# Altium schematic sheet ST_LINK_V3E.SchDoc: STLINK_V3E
size A3; Date: Not used; ApprovedBy: Not used; CheckedBy: Not used; Author: Not used; CompanyName: STMicroelectronics; DrawnBy: Not used; Engineer: Not used; Organization: Not used; Address1: Not used; Address2: Not used; Address3: Not used; Address4: Not used; DocumentNumber: 10; Revision: Not used; SheetNumber: 9; SheetTotal: 9
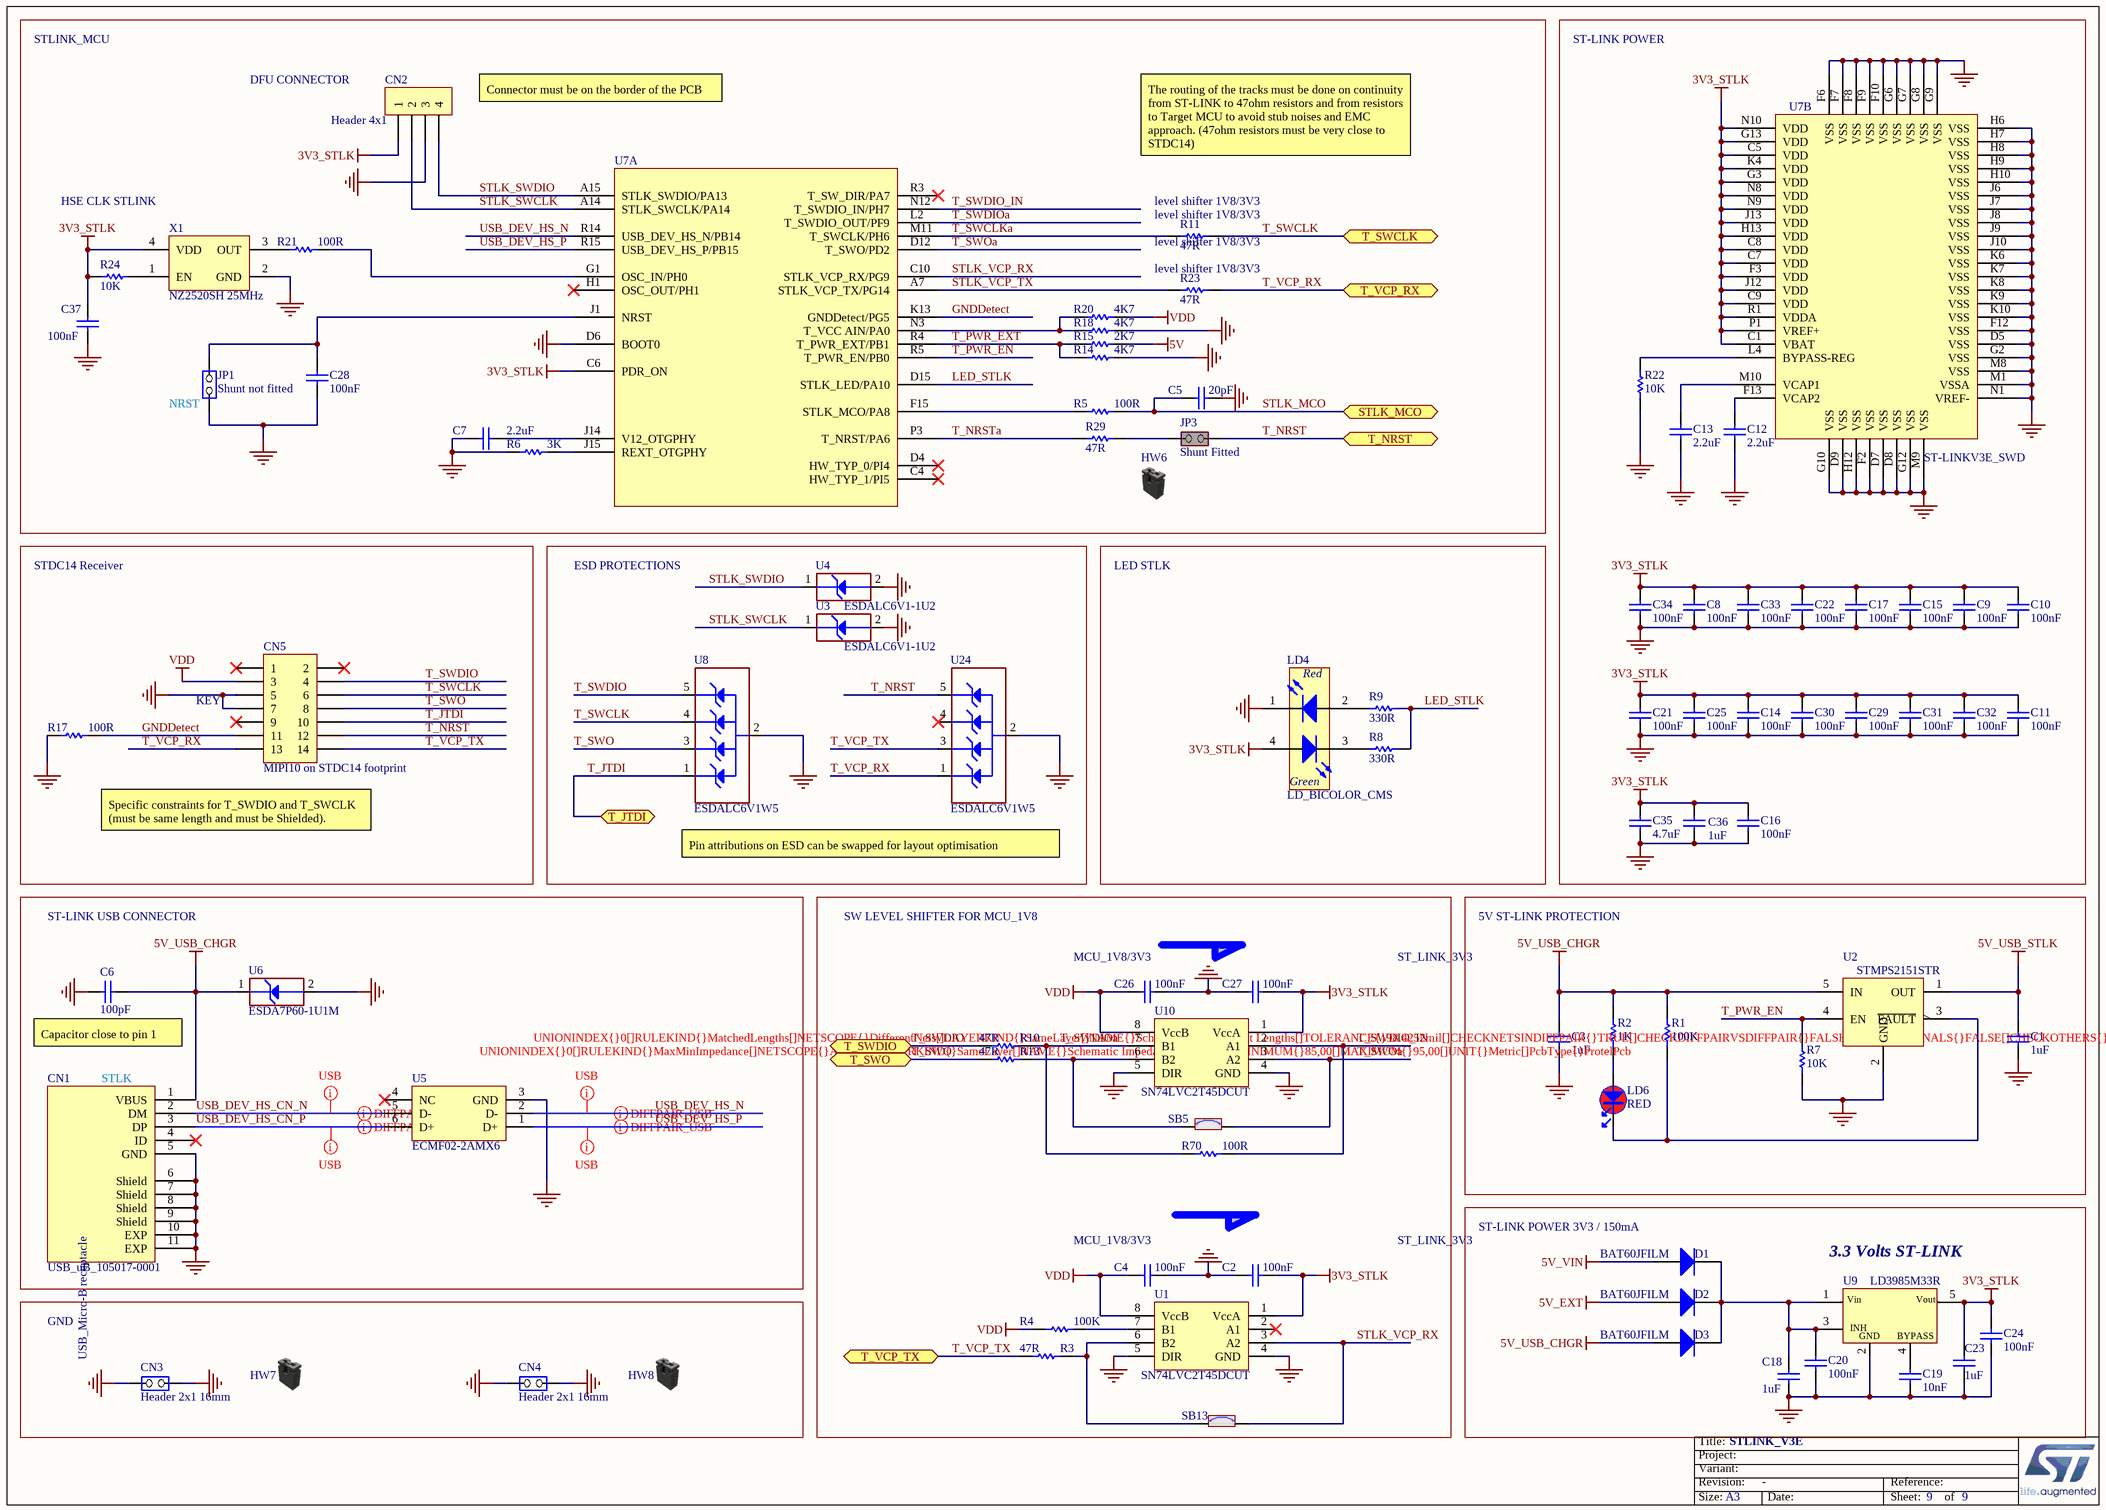
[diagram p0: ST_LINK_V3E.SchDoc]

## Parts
C1  value 1uF  [C0603]  (hidden comment: Capacitor)
C2  value 100nF  [C0603]  (hidden comment: Capacitor)
C3  value 1uF  [C0603]  (hidden comment: Capacitor)
C4  value 100nF  [C0603]  (hidden comment: Capacitor)
C5  value 20pF  [C0402]  (hidden comment: Capacitor)
C6  value 100pF  [C0402]  (hidden comment: Capacitor)
C7  value 2.2uF  [C0603]  (hidden comment: Capacitor)
C8  value 100nF  [C0402]  (hidden comment: Capacitor)
C9  value 100nF  [C0402]  (hidden comment: Capacitor)
C10  value 100nF  [C0402]  (hidden comment: Capacitor)
C11  value 100nF  [C0402]  (hidden comment: Capacitor)
C12  value 2.2uF  [C0603]  (hidden comment: Capacitor)
C13  value 2.2uF  [C0603]  (hidden comment: Capacitor)
C14  value 100nF  [C0402]  (hidden comment: Capacitor)
C15  value 100nF  [C0402]  (hidden comment: Capacitor)
C16  value 100nF  [C0402]  (hidden comment: Capacitor)
C17  value 100nF  [C0402]  (hidden comment: Capacitor)
C18  value 1uF  [C0603]  (hidden comment: Capacitor)
C19  value 10nF  [C0402]  (hidden comment: Capacitor)
C20  value 100nF  [C0402]  (hidden comment: Capacitor)
C21  value 100nF  [C0402]  (hidden comment: Capacitor)
C22  value 100nF  [C0402]  (hidden comment: Capacitor)
C23  value 1uF  [C0603]  (hidden comment: Capacitor)
C24  value 100nF  [C0402]  (hidden comment: Capacitor)
C25  value 100nF  [C0402]  (hidden comment: Capacitor)
C26  value 100nF  [C0603]  (hidden comment: Capacitor)
C27  value 100nF  [C0603]  (hidden comment: Capacitor)
C28  value 100nF  [C0402]  (hidden comment: Capacitor)
C29  value 100nF  [C0402]  (hidden comment: Capacitor)
C30  value 100nF  [C0402]  (hidden comment: Capacitor)
C31  value 100nF  [C0402]  (hidden comment: Capacitor)
C32  value 100nF  [C0402]  (hidden comment: Capacitor)
C33  value 100nF  [C0402]  (hidden comment: Capacitor)
C34  value 100nF  [C0402]  (hidden comment: Capacitor)
C35  value 4.7uF  [C0603]  (hidden comment: Capacitor)
C36  value 1uF  [C0603]  (hidden comment: Capacitor)
C37  value 100nF  [C0402]  (hidden comment: Capacitor)
CN1  value USB_uB_105017-0001  [CON_USBMICROB_MOLEX_105017-0001_H2P90]  (hidden comment: USB_uB_105017.0001)
CN2  Header 4x1  [CON_SAMTEC_TSW-104-07-G-S]
CN3  value Header 2x1 16mm  [CON_SAMTEC_TSW-102-09-X-S]  (hidden comment: Jumper_Header 2x1)
CN4  value Header 2x1 16mm  [CON_SAMTEC_TSW-102-09-X-S]  (hidden comment: Jumper_Header 2x1)
CN5  value MIPI10 on STDC14 footprint  [CON_STDC14_Receiver_MEDIUM_WITH_MIPI10_3D]  (hidden comment: Header 7x2)
D1  BAT60JFILM  [DIO_SOD323]
D2  BAT60JFILM  [DIO_SOD323]
D3  BAT60JFILM  [DIO_SOD323]
HW6  Shunt Black 2.54mm  (value not drawn)  (mechanical)
HW7  Shunt Black 2.54mm  (value not drawn)  (mechanical)
HW8  Shunt Black 2.54mm  (value not drawn)  (mechanical)
JP1  value Shunt not fitted  [CON_SAMTEC_TSW-102-07-G-S]  (hidden comment: Jumper_Header 2x1)
JP3  value Shunt Fitted  [CON_SAMTEC_TSW-102-07-G-S]  (hidden comment: Jumper_Header 2x1 Fitted)
LD4  LD_BICOLOR_CMS  [LED_BI-GR_HSMF-A201-A00J1]
LD6  value RED  [LED_0603_RED]  (hidden comment: LED_red)
R1  value 100K  [R0603]  (hidden comment: Resistor)
R2  value 1K  [R0603]  (hidden comment: Resistor)
R3  value 47R  [R0402]  (hidden comment: Resistor)
R4  value 100K  [R0603]  (hidden comment: Resistor)
R5  value 100R  [R0402]  (hidden comment: Resistor)
R6  value 3K  [R0402]  (hidden comment: Resistor)
R7  value 10K  [R0603]  (hidden comment: Resistor)
R8  value 330R  [R0603]  (hidden comment: Resistor)
R9  value 330R  [R0603]  (hidden comment: Resistor)
R10  value 47R  [R0402]  (hidden comment: Resistor)
R11  value 47R  [R0402]  (hidden comment: Resistor)
R13  value 47R  [R0402]  (hidden comment: Resistor)
R14  value 4K7  [R0402]  (hidden comment: Resistor)
R15  value 2K7  [R0402]  (hidden comment: Resistor)
R17  value 100R  [R0402]  (hidden comment: Resistor)
R18  value 4K7  [R0402]  (hidden comment: Resistor)
R20  value 4K7  [R0402]  (hidden comment: Resistor)
R21  value 100R  [R0402]  (hidden comment: Resistor)
R22  value 10K  [R0402]  (hidden comment: Resistor)
R23  value 47R  [R0402]  (hidden comment: Resistor)
R24  value 10K  [R0402]  (hidden comment: Resistor)
R29  value 47R  [R0402]  (hidden comment: Resistor)
R70  value 100R  [R0402]  (hidden comment: Resistor)
SB5  SB_ON  [SOLDER-BRIDGE_R0603-0R]  (value not drawn)
SB13  SB_ON  [SOLDER-BRIDGE_R0603-0R]  (value not drawn)
U1  SN74LVC2T45DCUT  [ICC_VSSOP8_DCU_R-PDSO-G8_2X2P30_P050]
U2  STMPS2151STR  [MOS_SOT23-5L]
U3  value ESDALC6V1-1U2  [ESD_ST0201]  (hidden comment: ESD-TRANSIL)
U4  value ESDALC6V1-1U2  [ESD_ST0201]  (hidden comment: ESD-TRANSIL)
U5  ECMF02-2AMX6  [ESD_QFN-6L_1P7X1P5_P050]
U6  value ESDA7P60-1U1M  [ESD_QFN2_1P6X1_P125]  (hidden comment: ESD-TRANSIL)
U7  ST-LINKV3E_SWD  [ICC_UFBGA201_176+25_10X10_P065]  (parts A,B of 2)
U8  ESDALC6V1W5  [ESD_SOT323-5L]
U9  LD3985M33R  [REG_SOT23-5L]
U10  SN74LVC2T45DCUT  [ICC_VSSOP8_DCU_R-PDSO-G8_2X2P30_P050]
U24  ESDALC6V1W5  [ESD_SOT323-5L]
X1  value NZ2520SH 25MHz  [OSC_NDK_NZ2520SB_4P]  (hidden comment: OSCILLATOR_4_PINS)

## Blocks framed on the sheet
ST-LINK POWER: C8-C17 C21 C22 C25 C29-C36 R22 U7
ESD PROTECTIONS: U3 U4 U8 U24
LED STLK: LD4 R8 R9
5V ST-LINK PROTECTION: C1 C3 LD6 R1 R2 R7 U2
3.3 Volts ST-LINK: C18-C20 C23 C24 D1-D3 U9
GND: CN3 CN4 HW7 HW8

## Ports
STLK_MCO, T_JTDI (bidir), T_NRST, T_SWCLK, T_SWDIO, T_SWO, T_VCP_RX, T_VCP_TX

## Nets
3V3_STLK: C2.2 C8.2 C9.2 C10.2 C11.2 C14.2 C15.2 C16.2 C17.2 C21.2 C22.2 C23.2 C24.2 C25.2 C27.2 C29.2 C30.2 C31.2 C32.2 C33.2 C34.2 C35.2 C36.2 C37.2 CN2.1 LD4.4(YellowGreen_anode) R24.1 U1.1(VccA) U7.C1(VBAT) U7.C5(VDD) U7.C6(PDR_ON) U7.C7(VDD) U7.C8(VDD) U7.C9(VDD) U7.F3(VDD) U7.G3(VDD) U7.G13(VDD) U7.H13(VDD) U7.J12(VDD) U7.J13(VDD) U7.K4(VDD) U7.N8(VDD) U7.N9(VDD) U7.N10(VDD) U7.P1(VREF+) U7.R1(VDDA) U9.5(Vout) U10.1(VccA) X1.4(VDD)
5V: R15.1
5V_EXT: D2.1(A)
5V_USB_CHGR: C3.2 C6.2 CN1.1(VBUS) D3.1(A) R1.2 R2.2 U2.5(IN) U6.1(IO1)
5V_USB_STLK: C1.2 U2.1(OUT)
5V_VIN: D1.1(A)
GND: C1.1 C2.1 C3.1 C4.2 C5.1 C6.1 C7.1 C8.1 C9.1 C10.1 C11.1 C12.1 C13.1 C14.1 C15.1 C16.1 C17.1 C18.2 C19.1 C20.1 C21.1 C22.1 C23.1 C24.1 C25.1 C26.2 C27.1 C28.1 C29.1 C30.1 C31.1 C32.1 C33.1 C34.1 C35.1 C36.1 C37.1 CN1.5(GND) CN1.6(Shield) CN1.7(Shield) CN1.8(Shield) CN1.9(Shield) CN1.10(EXP) CN1.11(EXP) CN2.3 CN3.1(COMMON) CN3.2(NO) CN4.1(COMMON) CN4.2(NO) CN5.5 CN5.7 JP1.1(COMMON) LD4.1(RED_cathode) R6.1 R7.2 R14.1 R17.1 R18.2 R22.1 U1.4(GND) U1.5(DIR) U2.2(GND) U3.2(GND) U4.2(GND) U5.3(GND) U6.2(GND) U7.D5(VSS) U7.D6(BOOT0) U7.D7(VSS) U7.D8(VSS) U7.D9(VSS) U7.F2(VSS) U7.F6(VSS) U7.F7(VSS) U7.F8(VSS) U7.F9(VSS) U7.F10(VSS) U7.F12(VSS) U7.G2(VSS) U7.G6(VSS) U7.G7(VSS) U7.G8(VSS) U7.G9(VSS) U7.G10(VSS) U7.G12(VSS) U7.H6(VSS) U7.H7(VSS) U7.H8(VSS) U7.H9(VSS) U7.H10(VSS) U7.H12(VSS) U7.J6(VSS) U7.J7(VSS) U7.J8(VSS) U7.J9(VSS) U7.J10(VSS) U7.K6(VSS) U7.K7(VSS) U7.K8(VSS) U7.K9(VSS) U7.K10(VSS) U7.M1(VSSA) U7.M8(VSS) U7.M9(VSS) U7.N1(VREF-) U8.2(GND) U9.2(GND) U10.4(GND) U10.5(DIR) U24.2(GND) X1.2(GND)
VDD: C4.1 C26.1 CN5.3 R4.2 R20.2 U1.8(VccB) U10.8(VccB)
GNDDetect: CN5.11 R17.2 U7.K13(GNDDetect/PG5)
LED_STLK: R8.2 R9.2 U7.D15(STLK_LED/PA10)
STLK_MCO: C5.2 R5.2 ; port STLK_MCO
STLK_SWCLK: CN2.2 U3.1(IO1) U7.A14(STLK_SWCLK/PA14)
STLK_SWDIO: CN2.4 U4.1(IO1) U7.A15(STLK_SWDIO/PA13)
STLK_VCP_RX: SB13.1 U1.3(A2) U7.C10(STLK_VCP_RX/PG9)
STLK_VCP_TX: R23.1 U7.A7(STLK_VCP_TX/PG14)
T_JTDI: CN5.10 U8.1(IO1) ; port T_JTDI
T_NRST: CN5.12 JP3.2(NO) U24.5(IO4) ; port T_NRST
T_NRSTa: R29.1 U7.P3(T_NRST/PA6)
T_PWR_EN: R7.1 U2.4(EN) U7.R5(T_PWR_EN/PB0)
T_PWR_EXT: R14.2 R15.2 U7.R4(T_PWR_EXT/PB1)
T_SWCLK: CN5.6 R11.2 U8.4(IO3) ; port T_SWCLK
T_SWCLKa: R11.1 U7.M11(T_SWCLK/PH6)
T_SWDIO: CN5.4 R10.1 U8.5(IO4) ; port T_SWDIO
T_SWDIO_IN: R70.2 U7.N12(T_SWDIO_IN/PH7) U10.2(A1)
T_SWDIOa: R10.2 R70.1 U7.L2(T_SWDIO_OUT/PF9) U10.7(B1)
T_SWO: CN5.8 R13.1 U8.3(IO2) ; port T_SWO
T_SWOa: SB5.1 U7.D12(T_SWO/PD2) U10.3(A2)
T_VCP_RX: CN5.13 R23.2 U24.1(IO1) ; port T_VCP_RX
T_VCP_TX: CN5.14 R3.1 U24.3(IO2) ; port T_VCP_TX
USB_DEV_HS_CN_N: CN1.2(DM) U5.5(D-)
USB_DEV_HS_CN_P: CN1.3(DP) U5.6(D+)
USB_DEV_HS_N: U5.2(D-) U7.R14(USB_DEV_HS_N/PB14)
USB_DEV_HS_P: U5.1(D+) U7.R15(USB_DEV_HS_P/PB15)
NetC7_2: C7.2 U7.J14(V12_OTGPHY)
NetC12_2: C12.2 U7.F13(VCAP2)
NetC13_2: C13.2 U7.M10(VCAP1)
NetC18_1: C18.1 C20.2 D1.2(K) D2.2(K) D3.2(K) U9.1(Vin) U9.3(CE)
NetC19_2: C19.2 U9.4(BYPASS)
NetC28_2: C28.2 JP1.2(NO) U7.J1(NRST)
NetJP3_1: JP3.1(COMMON) R29.2
NetLD4_2: LD4.2(Red_anode) R9.1
NetLD4_3: LD4.3(YellowGreen_cathode) R8.1
NetLD6_1: LD6.1 R2.1
NetLD6_2: LD6.2 R1.1 U2.3(~{FAULT})
NetR3_2: R3.2 SB13.2 U1.6(B2)
NetR4_1: R4.1 U1.7(B1)
NetR5_1: R5.1 U7.F15(STLK_MCO/PA8)
NetR6_2: R6.2 U7.J15(REXT_OTGPHY)
NetR13_2: R13.2 SB5.2 U10.6(B2)
NetR18_1: R18.1 R20.1 U7.N3(T_VCC_AIN/PA0)
NetR21_1: R21.1 X1.3(OUT)
NetR21_2: R21.2 U7.G1(OSC_IN/PH0)
NetR22_2: R22.2 U7.L4(BYPASS-REG)
NetR24_2: R24.2 X1.1(EN)

Not connected (* = marked no-connect by the designer): CN1 4(ID)*; CN5 1* 2* 9*; U1 2(A1)*; U5 4(NC)*; U7 C4(HW_TYP_1/PI5)* D4(HW_TYP_0/PI4)* H1(OSC_OUT/PH1)* R3(T_SW_DIR/PA7)*; U24 4(IO3)*

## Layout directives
differential pair; rule Impedance Constraint [Min = 85.00    Max = 95.00    ]: USB_DEV_HS_CN_N, USB_DEV_HS_CN_P, USB_DEV_HS_N, USB_DEV_HS_P
rule Undefined; rule Matched Net Lengths [Tolerance = 2.5mm]; rule Impedance Constraint [Min = 85.00    Max = 95.00    ]: USB_DEV_HS_N
rule Undefined; rule Matched Net Lengths [Tolerance = 0.2mm]; rule Impedance Constraint [Min = 85.00    Max = 95.00    ]: USB_DEV_HS_CN_N, USB_DEV_HS_CN_P, USB_DEV_HS_P

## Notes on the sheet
- STLINK_MCU
- DFU CONNECTOR
- (near CN2) Connector must be on the border of the PCB
- The routing of the tracks must be done on continuity from ST-LINK to 47ohm resistors and from resistors to Target MCU to avoid stub noises and EMC approach. (47ohm resistors must be very close to STDC14)
- HSE CLK STLINK
- (near R11) level shifter 1V8/3V3
- level shifter 1V8/3V3
- (near JP1) NRST
- STDC14 Receiver
- (near CN5) KEY
- Specific constraints for T_SWDIO and T_SWCLK (must be same length and must be Shielded).
- Pin attributions on ESD can be swapped for layout optimisation
- ST-LINK USB CONNECTOR
- SW LEVEL SHIFTER FOR MCU_1V8
- MCU_1V8/3V3
- ST_LINK_3V3
- (near C6) Capacitor close to pin 1
- (near CN1) STLK
- ST-LINK POWER 3V3 / 150mA

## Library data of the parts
C1 C3 C18 = MCD-00238: Capacitor, MLCC, 1uF, 6V3, X5R, 10%, 0603, T=0,8mm; Manufacturer_Part_Number: CC0603KRX5R5BB105; Manufacturer: YAGEO; Provided_By: SUBCO; ECCN_US: EAR99; ECCN_EU: NEC
C2 C4 = MCD-00211: Capacitor, MLCC, 100nF, 16V, X7R, 10%, 0603, T=0,8mm; Manufacturer_Part_Number: CC0603KRX7R7BB104; Manufacturer: YAGEO; Provided_By: SUBCO; ECCN_US: EAR99; ECCN_EU: NEC
C5 = MCD-00016: Capacitor, MLCC, 20pF, 50V, NPO, 5%, 0402, T=0,5mm; Manufacturer_Part_Number: CC0402JRNPO9BN200; Manufacturer: YAGEO; Provided_By: SUBCO; ECCN_US: EAR99; ECCN_EU: NEC
C6 = MCD-00205: Capacitor, MLCC, 100pF, 50V, NPO, 5%, 0402, T=0,5mm; Manufacturer_Part_Number: CC0402JRNPO9BN101; Manufacturer: YAGEO; Provided_By: SUBCO; ECCN_US: EAR99; ECCN_EU: NEC
C7 C12 C13 = MCD-00012: Capacitor, MLCC, 2.2uF, 10V, X5R, 10%, 0603, T=0,8mm; Manufacturer_Part_Number: CC0603KRX5R6BB225; Manufacturer: YAGEO; Alternate_Manufacturer_Part_Number: C0603C225K8PACTU; Alternate_Manufacturer: KEMET; Provided_By: SUBCO; ECCN_US: EAR99; ECCN_EU: NEC
C8-C11 C14-C17 C20-C22 C24 C25 C28-C34 C37 = MCD-00102: Capacitor, MLCC, 100nF, 16V, X7R, 10%, 0402, T=0,5mm; Manufacturer_Part_Number: CC0402KRX7R7BB104; Manufacturer: YAGEO; Alternate_Manufacturer_Part_Number: GCM155R71C104KA55D; Alternate_Manufacturer: MURATA; Provided_By: SUBCO; ECCN_US: EAR99; ECCN_EU: NEC
C19 = MCD-00011: Capacitor, MLCC, 10nF, 16V, X7R, 10%, 0402, T=0.5mm; Manufacturer_Part_Number: CC0402KRX7R7BB103; Manufacturer: YAGEO; Provided_By: SUBCO; ECCN_US: EAR99; ECCN_EU: NEC
C23 C36 = MCD-00010: Capacitor, MLCC, 1uF, 16V, X5R, 10%, 0603, T=0,8mm; Manufacturer_Part_Number: CC0603KRX5R7BB105; Manufacturer: YAGEO; Provided_By: SUBCO; ECCN_US: EAR99; ECCN_EU: NEC
C26 C27 = MCD-00237: Capacitor, MLCC, 100nF, 6V3, X5R, 10%, 0603, T=0,8mm; Manufacturer_Part_Number: CC0603KRX5R5BB104; Manufacturer: YAGEO; Provided_By: SUBCO; ECCN_US: EAR99; ECCN_EU: NEC
C35 = MCD-00009: Capacitor, MLCC, 4.7uF, 16V, X5R, 10%, 0603, T=0.8mm; Manufacturer_Part_Number: CC0603KRX5R7BB475; Manufacturer: YAGEO; Provided_By: SUBCO; ECCN_US: EAR99; ECCN_EU: NEC
CN1 = MCD-00028: USB-MICRO-B, 0.65mm, RA, SMT, Bottom Mount,; Manufacturer_Part_Number: 1050170001; Manufacturer: MOLEX; Part_Type: Connector; Provided_By: SUBCO
CN2 = MCD-00029: Header, 4x1, 2,54mm, VR, TH, Height 5.84mm/2.54mm; Manufacturer_Part_Number: TSW-104-07-x-S; Manufacturer: SAMTEC; Part_Type: Connector; Provided_By: SUBCO
CN3 CN4 = MCD-00214: Header, 2x1, 2,54mm, VR, TH, Height 5.84mm/10.16mm; Part_Type: Connector; Manufacturer_Part_Number: TSW-102-09-x-S; Manufacturer: SAMTEC; Provided_By: SUBCO
CN5 = MCD-01226: Header 5x2, 1.27mm, Dual row, Straight, Surface mount, vertical male connector. 3.05mm lead. Mates with FFSD connector. Footprint compatible with FTSH-107-01-L-DV,-K,-A,-P,-ES (STDC14 MEDIUM); Manufacturer_Part_Number: FTSH-105-01-L-DV-K; Manufacturer: SAMTEC; Alternate_Manufacturer_Part_Number: P127B-2x05MGF-079-1A; Alternate_Manufacturer: JIUBABA; Provided_By: SUBCO
D1-D3 = MCD-00034: Manufacturer: STMICROELECTRONICS; Part_Type: Diode; BMS_Part_Number: 9151097; Provided_By: SUBCO with ST control; ECCN_US: EAR99; ECCN_EU: NEC
HW6-HW8 = MCD-00043: SHUNT 2.54mm BLACK; Manufacturer_Part_Number: SNT-100-BK-G; Manufacturer: SAMTEC; Part_Type: Mechanical; Alternate_Manufacturer_Part_Number: 316102S111A; Alternate_Manufacturer: JIUBABA; Provided_By: SUBCO
JP1 = MCD-00045: Header, 2x1, 2,54mm, VR, TH, Height 5.84mm/2.54mm; Part_Type: Connector; Manufacturer_Part_Number: TSW-102-07-x-S; Manufacturer: SAMTEC; Alternate_Manufacturer_Part_Number: 313102S111116;313102S111116; Alternate_Manufacturer: JIUBABA; LIANYI; Provided_By: SUBCO
JP3 = MCD-00683: Header, 2x1, 2,54mm, VR, TH, Height 5.84mm/2.54mm - Shunt Fitted by default; Part_Type: Connector; Manufacturer_Part_Number: TSW-102-07-x-S; Manufacturer: SAMTEC; Alternate_Manufacturer_Part_Number: 313102S111116; Alternate_Manufacturer: LIANYI; Provided_By: SUBCO
LD4 = MCD-00051: LED Bicolor; Part_Type: Display; Manufacturer_Part_Number: HSMF-A201-A00J1; Manufacturer: AVAGO TECHNOLOGIES; Alternate_Manufacturer_Part_Number: LE-RGW35280; Alternate_Manufacturer: EVERLUCK; Provided_By: SUBCO; ECCN_US: EAR99; ECCN_EU: NEC
LD6 = MCD-00049: LED, Red, 0603; Manufacturer_Part_Number: 19-213-R6C-AP1Q2B/3T; Manufacturer: EVERLIGHT; Part_Type: Display; Provided_By: SUBCO; ECCN_US: EAR99; ECCN_EU: NEC
R1 R4 = MCD-00223: Resistor,100K,0603,1%,1/10W; Manufacturer_Part_Number: RC0603FR-07100KL; Manufacturer: YAGEO; Provided_By: SUBCO; ECCN_US: EAR99; ECCN_EU: NEC
R2 = MCD-00070: Resistor,1K,0603,1%,1/10W; Manufacturer_Part_Number: RC0603FR-071KL; Manufacturer: YAGEO; Provided_By: SUBCO; ECCN_US: EAR99; ECCN_EU: NEC
R3 R10 R11 R13 R23 R29 = MCD-00481: Resistor,47R,0402,1%,1/16W; Manufacturer_Part_Number: RC0402FR-0747RL; Manufacturer: YAGEO; Provided_By: SUBCO; ECCN_US: EAR99; ECCN_EU: NEC
R5 R17 R21 R70 = MCD-00119: Resistor,100R,0402,1%,1/16W; Manufacturer_Part_Number: RC0402FR-07100RL; Manufacturer: YAGEO; Provided_By: SUBCO; ECCN_US: EAR99; ECCN_EU: NEC
R6 = MCD-00185: Resistor,3K,0402,1%,1/16W; Manufacturer_Part_Number: RC0402FR-073KL; Manufacturer: YAGEO; Provided_By: SUBCO; ECCN_US: EAR99; ECCN_EU: NEC
R7 = MCD-00220: Resistor,10K,0603,1%,1/10W; Manufacturer_Part_Number: RC0603FR-0710KL; Manufacturer: YAGEO; Provided_By: SUBCO; ECCN_US: EAR99; ECCN_EU: NEC
R8 R9 = MCD-00197: Resistor,330R,0603,1%,1/10W; Manufacturer_Part_Number: RC0603FR-07330RL; Manufacturer: YAGEO; BMS_Part_Number: 9129729; Provided_By: SUBCO; ECCN_US: EAR99; ECCN_EU: NEC
R14 R18 R20 = MCD-00065: Resistor,4K7,0402,1%,1/16W; Manufacturer_Part_Number: RC0402FR-074K7L; Manufacturer: YAGEO; Alternate_Manufacturer_Part_Number: RT0402FRE074K7L; Provided_By: SUBCO; ECCN_US: EAR99; ECCN_EU: NEC
R15 = MCD-00055: Resistor,2K7,0402,1%,1/16W; Manufacturer_Part_Number: RC0402FR-072K7L; Manufacturer: YAGEO; Provided_By: SUBCO; ECCN_US: EAR99; ECCN_EU: NEC
R22 R24 = MCD-00053: Resistor,10K,0402,1%,1/16W; Manufacturer_Part_Number: RC0402FR-0710KL; Manufacturer: YAGEO; Provided_By: SUBCO; ECCN_US: EAR99; ECCN_EU: NEC
SB5 SB13 = MCD-00071: Solder Bridge ON; Part_Type: Mechanical; Manufacturer_Part_Number: RC0603JR-070RL; Manufacturer: YAGEO; Provided_By: SUBCO
U1 U10 = MCD-00264: Dual bit dual supply bus transceiver; Part_Type: IC; Manufacturer: TEXAS INSTRUMENTS; Provided_By: SUBCO; ECCN_US: EAR99; ECCN_EU: NEC
U2 = MCD-00159: 500mA, Enhanced single channel power switches with active high enable pin; Part_Type: IC; Manufacturer: STMICROELECTRONICS; Alternate_Manufacturer_Part_Number: TPS2051C; Alternate_Manufacturer: TEXAS INSTRUMENTS; BMS_Part_Number: 9159009; Provided_By: SUBCO with ST control; ECCN_US: EAR99; ECCN_EU: NEC
U3 U4 = MCD-00170: ESD protection 6V1; Part_Type: Diode; Manufacturer: STMICROELECTRONICS; BMS_Part_Number: 9151132; Provided_By: SUBCO with ST control; ECCN_US: EAR99; ECCN_EU: NEC
U5 = MCD-00649: Common mode filter with ESD protection for USB 2.0 interface; Part_Type: Diode; Manufacturer: STMICROELECTRONICS; BMS_Part_Number: 9151138; Provided_By: SUBCO with ST control; ECCN_US: EAR99; ECCN_EU: NEC
U6 = MCD-00251: High power transient voltage suppressor, 7V breakdown; Part_Type: Diode; Manufacturer: STMICROELECTRONICS; BMS_Part_Number: 9179042; Provided_By: SUBCO with ST control; ECCN_US: EAR99; ECCN_EU: NEC
U7 = MCD-00596: STM32F723IEK  (STM32F7) BGA176; Part_Type: IC; Manufacturer_Part_Number: STM32F723IEK6; Manufacturer: STMICROELECTRONICS; BMS_Part_Number: 9175300; Provided_By: SUBCO with ST control; ECCN_US: 3A991A2; ECCN_EU: NEC
U8 U24 = MCD-00136: Dual Transil array for ESD protection; Part_Type: Diode; Manufacturer: STMICROELECTRONICS; BMS_Part_Number: 9151112; Provided_By: SUBCO with ST control; ECCN_US: EAR99; ECCN_EU: NEC
U9 = MCD-00086: Ultra low drop-low noise BiCMOS voltage, regulators low ESR capacitors compatible; Manufacturer: STMICROELECTRONICS; Part_Type: IC; BMS_Part_Number: 9176161; Provided_By: SUBCO with ST control; ECCN_US: EAR99; ECCN_EU: NEC
X1 = MCD-00597: Oscillator 25Mhz, +-50ppm, Vcc:3.3V typ, square wave: [0.1Vcc;0.9Vcc], Enable pin, SMD; Manufacturer_Part_Number: NZ2520SH 25MHz END4869C; Manufacturer: NDK; Alternate_Manufacturer_Part_Number: NZ2520SB 25MHz END4869B; Part_Type: Crystal_Osc; BMS_Part_Number: 9157050; Provided_By: SUBCO; ECCN_US: EAR99; ECCN_EU: NEC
